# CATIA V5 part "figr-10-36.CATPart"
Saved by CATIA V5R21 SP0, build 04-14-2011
Part number: Part1
Bounding box of the stored display mesh (mm): x -322.306 to 0, y -118.205 to 88.531, z 0 to 101.949
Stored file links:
  D:\CATIA V5R21 E-RESOURCES\CATIA-V5R21\catia-v5r21-prt\c10-catia-v5r20-prt\c10-catia-v5r21-figr-10-36.CATPart
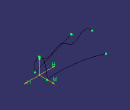
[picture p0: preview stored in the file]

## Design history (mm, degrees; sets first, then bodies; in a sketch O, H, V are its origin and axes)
Set1
  Curve1: Elements (vertex of Sketch2; vertex of Sketch1; vertex of Sketch3)
Body1 (main body)
  Sketch1 on zx-plane, origin (0, 0, 0), H (-1, 0, 0), V (0, 0, 1)
    spline S1 through (0, 96.336) (70.1946, 72.4244) (144.1119, 96.336) (203.5098, 63.985) (253.668, 92.1163) (322.3056, 72.4244)
    point P1 (0, 96.336)
    coincidence: P1 V
  Sketch2 on xy-plane, origin (0, 0, 0), H (1, 0, 0), V (0, 1, 0)
    point P1 (0, 47.0553)
    arc A1 centre (-78.7604, 671.3501) radius 629.2433 from (0, 47.0553) to (-315.9706, 88.5306) cw
    coincidence: P1 V
  Sketch3 on xy-plane, origin (0, 0, 0), H (1, 0, 0), V (0, 1, 0)
    line L1 (0, -26.5991) -> (-311.8959, -118.2048)
    point P1 (0, -26.5991)
    coincidence: P1 V
  Sketch4 on yz-plane, origin (0, 0, 0), H (0, 1, 0), V (0, 0, 1)
    point P1 (-26.5991, 0)
    point P2 (0, 58.544)
    point P3 (47.0553, 0)
    reference projected point E1 (47.0553, 0) from vertex of Sketch2
    reference projected point E2 (-26.5991, 0) from vertex of Sketch3
    spline S1 through (-26.5991, 0) (-29.9268, 35.6209) (0, 96.336) (47.0553, 0)
    reference projected point E3 (0, 96.336) from vertex of Sketch1
    point P4 (-26.5991, 0)
    point P5 (0, 96.336)
    point P6 (47.0553, 0)
    coincidence: P1 H, P3 H, E1 P3, P1 E2, P4 P1, P5 V, P6 P3, E3 S1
